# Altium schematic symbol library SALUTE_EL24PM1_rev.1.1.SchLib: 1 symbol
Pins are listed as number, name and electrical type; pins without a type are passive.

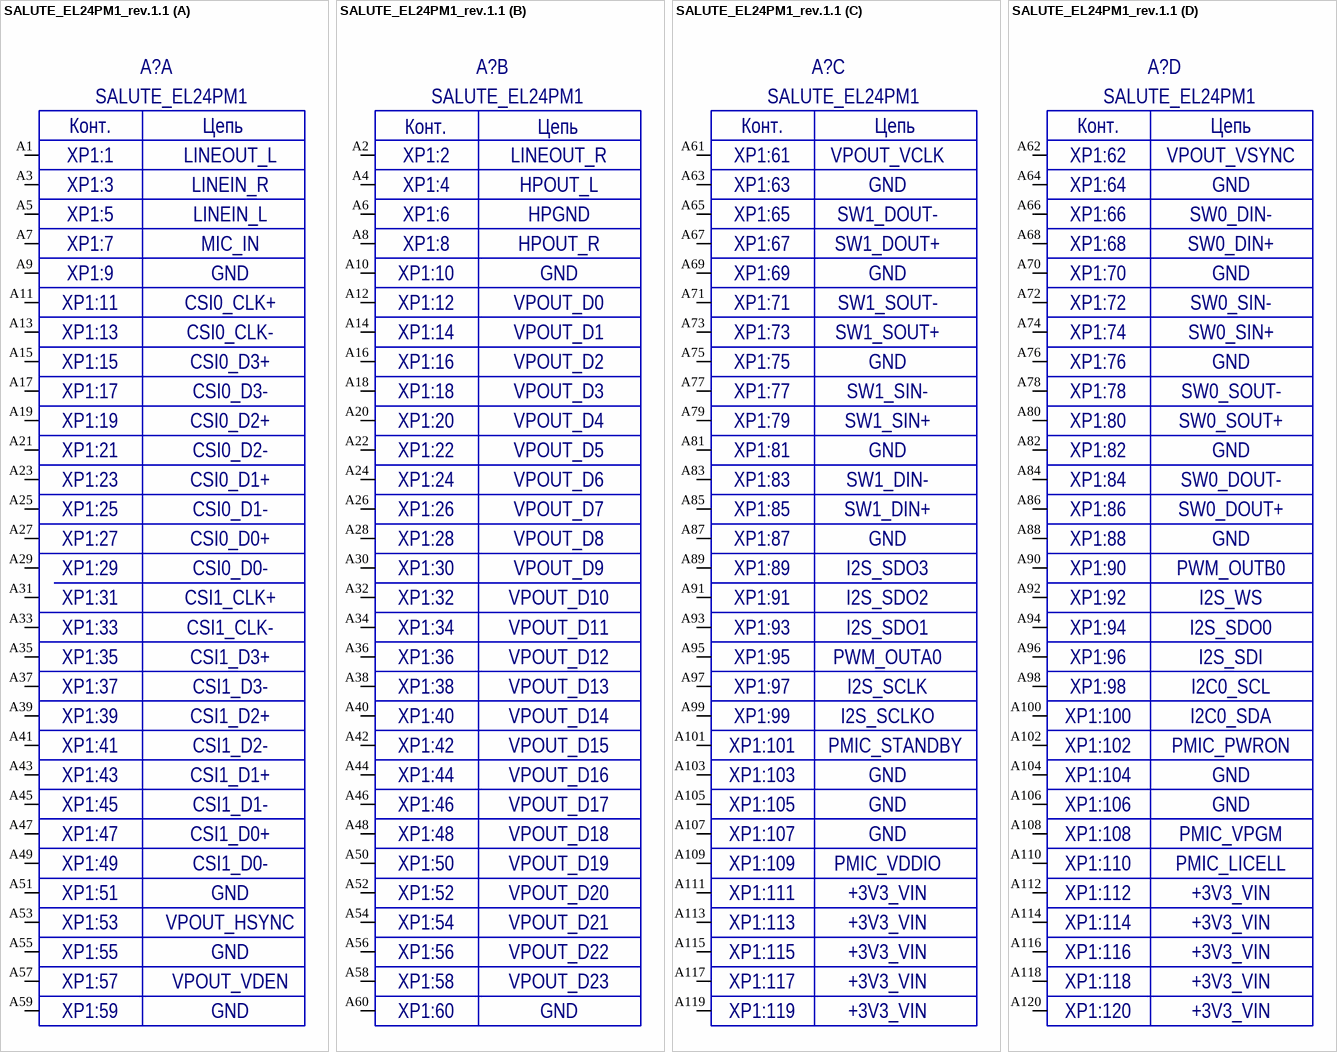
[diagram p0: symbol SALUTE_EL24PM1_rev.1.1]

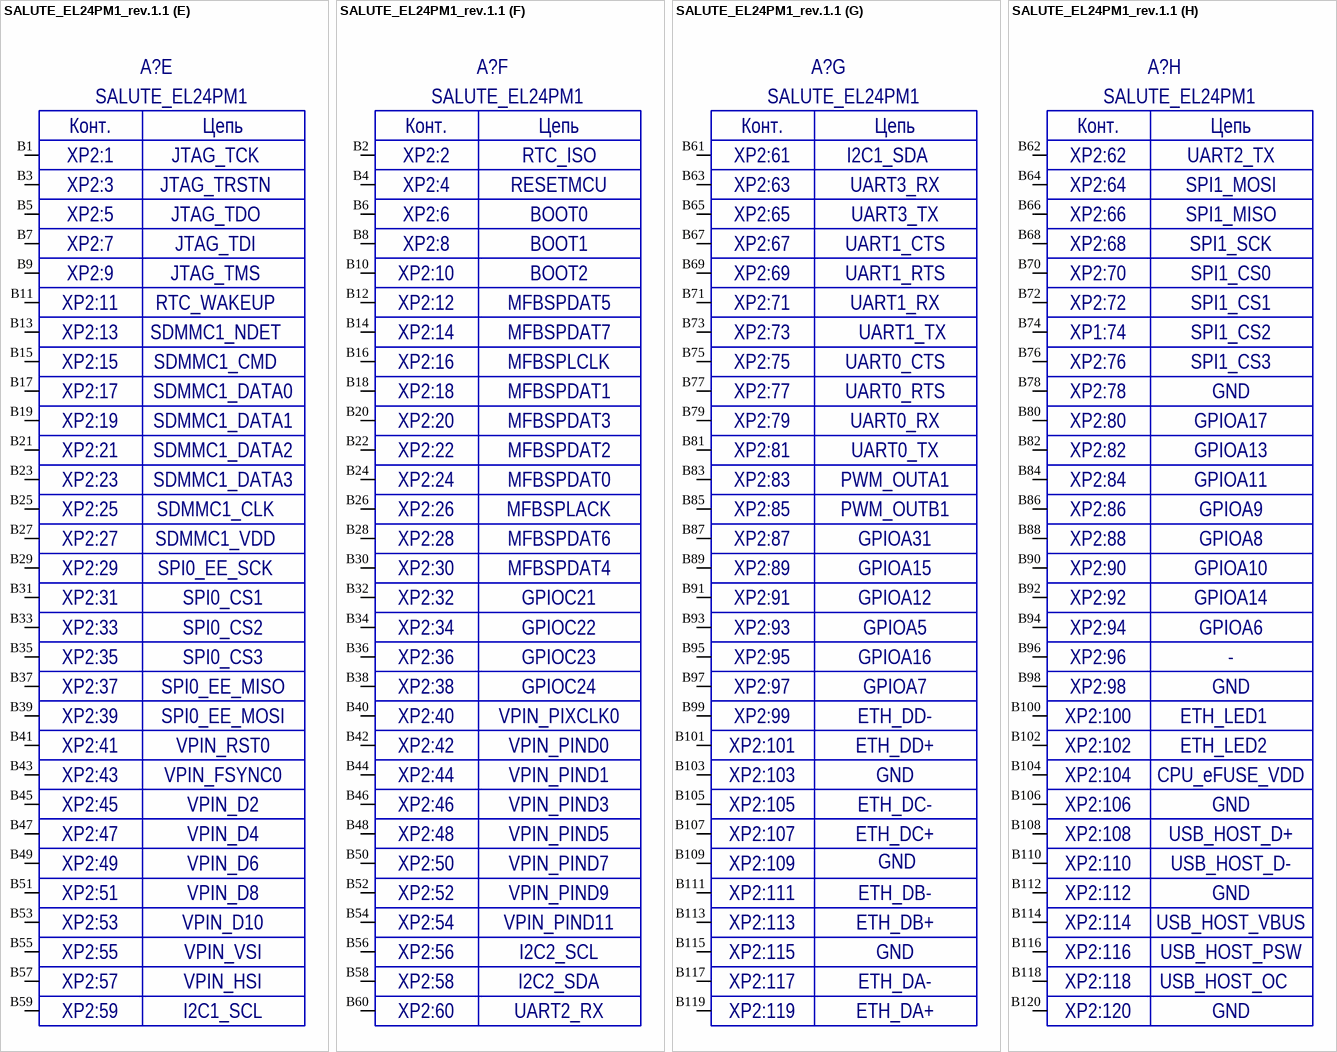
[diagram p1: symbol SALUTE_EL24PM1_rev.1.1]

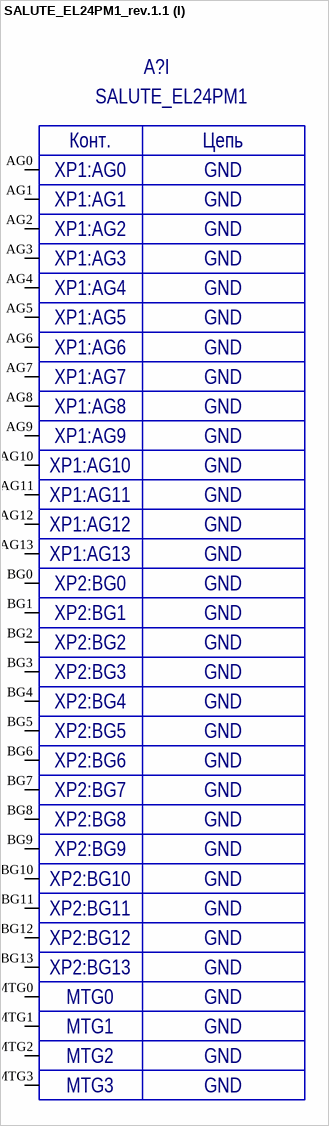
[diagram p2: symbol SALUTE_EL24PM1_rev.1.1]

## SALUTE_EL24PM1_rev.1.1
designator A?, comment SALUTE_EL24PM1
SOM 1892VM14YA; Manufacturer: АО НПЦ "ЭЛВИС"; Rev.: 1.1
footprint SALUTE_EL24PM1
part A pins: A1, A3, A5, A7, A9, A11, A13, A15, A17, A19, A21, A23, A25, A27, A29, A31, A33, A35, A37, A39, A41, A43, A45, A47, A49, A51, A53, A55, A57, A59
part B pins: A2, A4, A6, A8, A10, A12, A14, A16, A18, A20, A22, A24, A26, A28, A30, A32, A34, A36, A38, A40, A42, A44, A46, A48, A50, A52, A54, A56, A58, A60
part C pins: A61, A63, A65, A67, A69, A71, A73, A75, A77, A79, A81, A83, A85, A87, A89, A91, A93, A95, A97, A99, A101, A103, A105, A107, A109, A111, A113, A115, A117, A119
part D pins: A62, A64, A66, A68, A70, A72, A74, A76, A78, A80, A82, A84, A86, A88, A90, A92, A94, A96, A98, A100, A102, A104, A106, A108, A110, A112, A114, A116, A118, A120
part E pins: B1, B3, B5, B7, B9, B11, B13, B15, B17, B19, B21, B23, B25, B27, B29, B31, B33, B35, B37, B39, B41, B43, B45, B47, B49, B51, B53, B55, B57, B59
part F pins: B2, B4, B6, B8, B10, B12, B14, B16, B18, B20, B22, B24, B26, B28, B30, B32, B34, B36, B38, B40, B42, B44, B46, B48, B50, B52, B54, B56, B58, B60
part G pins: B61, B63, B65, B67, B69, B71, B73, B75, B77, B79, B81, B83, B85, B87, B89, B91, B93, B95, B97, B99, B101, B103, B105, B107, B109, B111, B113, B115, B117, B119
part H pins: B62, B64, B66, B68, B70, B72, B74, B76, B78, B80, B82, B84, B86, B88, B90, B92, B94, B96, B98, B100, B102, B104, B106, B108, B110, B112, B114, B116, B118, B120
part I pins: AG0, AG1, AG2, AG3, AG4, AG5, AG6, AG7, AG8, AG9, AG10, AG11, AG12, AG13, BG0, BG1, BG2, BG3, BG4, BG5, BG6, BG7, BG8, BG9, BG10, BG11, BG12, BG13, MTG0, MTG1, MTG2, MTG3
